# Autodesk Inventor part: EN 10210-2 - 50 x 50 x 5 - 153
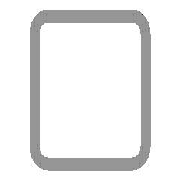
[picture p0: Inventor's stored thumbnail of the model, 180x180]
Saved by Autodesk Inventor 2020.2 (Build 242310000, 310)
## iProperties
Created: 2019-01
Part Number: EN 10210-2 - 50 x 50 x 5 - 153
Material: Stahl, weich
Description: Rohrleitung
Document SubType Name: Modeling
Standard: DIN
Designer: lutzd
Standard Revision: 2006-07
Standards Organization: DIN
Language: de-DE
Size Designation: 50 x 50 x 5
Categories: <MemberInstance><Categories><Category DisplayName="Profile" InternalName="089c4875-fa83-4c05-b084-43b9cc11f5ed" Mnemonic="GRDR"><CategoryParameter DisplayName="
Stock Number: 50 x 50 x 5
Mass: 1048.73 g
Surface Area: 535.429 cm^2
Volume: 133.596 cm^3
Density: 7.85 g/cm^3
Appearance: Semi-Polished(8)
IsCustomPart: 1
G_L: 153,000 mm
G_W: 50,000 mm
G_H: 50,000 mm
+AEAC450E-8B95-44FA-B5EC-5B93AA84A504+SCHNITTDETAIL1: Schnittwinkel 90,00 grd
+B1E53CEA-316B-4473-968A-23E09A69A433+SCHNITTDETAIL2: Schnittwinkel 90,00 grd
DocNumber: ADSK-014330
Folder: .
Dimensions: 50x50x153 mm
Mass: 1,049 kg
VLT_Material: Stahl, weich
_CCFamilyMember: 16
_CCFamilyDisplayName: DIN EN 10210-2 (USAS B17.1 quadratisch) - Rohrleitung — In Klammern angegebene Größen wurden aufgehoben
_FrameMemberDoc: Frame Member File
_Version: 15.0.0
_GetPNFromCC: 1
Title: Profil-Bauteil
Author: lutzd
Revision Number: -
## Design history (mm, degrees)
node "Startebene"
node "Endebene"
sketch "Skizze"
  geometry: L1 (-25, -17.5)-(-25, 17.5); L2 (-17.5, 25)-(17.5, 25); L3 (25, 17.5)-(25, -17.5); L4 (17.5, -25)-(-17.5, -25); L5 (-15, 20)-(15, 20); L6 (20, 15)-(20, -15); L7 (15, -20)-(-15, -20); L8 (-20, -15)-(-20, 15); L9 (0, 37.175)-(0, -37.175) reference; L10 (-37.175, 0)-(37.175, 0) reference; A1 r 7.5 centre (-17.5, -17.5) between (-25, -17.5) and (-17.5, -25); A2 r 7.5 centre (-17.5, 17.5) between (-17.5, 25) and (-25, 17.5); A3 r 7.5 centre (17.5, 17.5) between (25, 17.5) and (17.5, 25); A4 r 7.5 centre (17.5, -17.5) between (17.5, -25) and (25, -17.5); A5 r 5 centre (-15, -15) between (-20, -15) and (-15, -20); A6 r 5 centre (-15, 15) between (-15, 20) and (-20, 15); A7 r 5 centre (15, 15) between (20, 15) and (15, 20); A8 r 5 centre (15, -15) between (15, -20) and (20, -15)
  constraints: 16 end point, 16 point on circle, 16 tangent, 8 centre point, 6 equal radius, 4 parallel, 2 perpendicular, 2 other
  dimensions: "d7" = 7.5 radius of A1 (= G_IR); "d10" = 50 distance between parallel lines of L2 L4 (= G_H); "d11" = 50 distance between parallel lines of L1 L3 (= G_W); "d12" = 5 distance between parallel lines of L3 L6 (= G_T); "d15" = 25 distance between parallel lines of L2 L10 (= 0.5 x d10); "d16" = 25 distance between parallel lines of L9 L3 (= 0.5 x d11); "d19" = 5 radius of A5 (= G_T); "d20" = 5 distance between parallel lines of L4 L7 (= G_T)
extrude "Körper" new body sketch "Skizze" stored distance "d3" = 153 (= G_L); taper "d4" = 0 deg
node "Driven Length"
  sketch "Sketch3"
    geometry: L1 (0, 0)-(10, 0) reference
    constraints: 2 end point, 1 horizontal
  workplane "Work Plane3"
  sketch "Sketch4"
    geometry: L1 (-2, 50)-(12, 50) reference; L2 (-2, 203)-(12, 203) reference
    dimensions: "d18" = 153 distance between parallel lines of L1 L2 (derived)
workplane "Arbeitsebene4"
feature "Trennen1"
workplane "Arbeitsebene5"
feature "Trennen2"
body "Solid1"
other parameters: "G_W" = 50 [user parameter; used in 1 equation term], "G_H" = 50 [user parameter; used in 1 equation term], "G_T" = 5 [user parameter; used in 3 equation terms], "G_IR" = 7.5 [user parameter; used in 1 equation term], "G_L" = 153 (= d18) [user parameter; used in 1 equation term], "d14" = 203 (= G_OFFSET_END + B_L), "B_L" = 253 [user parameter; used in 1 equation term], "d17" = 90 deg
